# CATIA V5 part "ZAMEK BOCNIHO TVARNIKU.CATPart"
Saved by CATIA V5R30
Part number: ZAMEK BOCNIHO TVARNIKU
Bounding box of the stored display mesh (mm): x -1.29 to 19.5, y -8 to 17, z -7 to 7
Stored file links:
  C:\Users\ondra\Desktop\PŘÍLOHA P III\CATIA\ZAMEK BOCNIHO TVARNIKU.CATPart
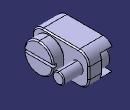
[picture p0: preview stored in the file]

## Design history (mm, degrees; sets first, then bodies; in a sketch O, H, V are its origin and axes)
Set1
  DatumSurface1 to DatumSurface36 "Z1899/8x"
  DatumSurface37 to DatumSurface64 "Z36/8x16"
  DatumSurface65 to DatumSurface93 "Z31/5x14"
  Plane1: type Offset, RefPlane zx-plane, Offset 17
  Join1: Elements (DatumSurface1; DatumSurface2; DatumSurface3; DatumSurface4; DatumSurface5; DatumSurface6; DatumSurface7; DatumSurface8; DatumSurface9; DatumSurface10; DatumSurface11; DatumSurface12; DatumSurface13; DatumSurface14; DatumSurface15; DatumSurface16; DatumSurface17; DatumSurface18; DatumSurface19; DatumSurface20; DatumSurface21; DatumSurface22; DatumSurface23; DatumSurface24; DatumSurface25; DatumSurface26; DatumSurface27; DatumSurface28; DatumSurface29; DatumSurface30; DatumSurface31; DatumSurface32; DatumSurface33; DatumSurface34; DatumSurface35; DatumSurface36)
  Join2: Elements (DatumSurface37; DatumSurface38; DatumSurface39; DatumSurface40; DatumSurface41; DatumSurface42; DatumSurface43; DatumSurface44; DatumSurface45; DatumSurface46; DatumSurface47; DatumSurface48; DatumSurface49; DatumSurface50; DatumSurface51; DatumSurface52; DatumSurface53; DatumSurface54; DatumSurface55; DatumSurface56; DatumSurface57; DatumSurface58; DatumSurface59; DatumSurface60; DatumSurface61; DatumSurface62; DatumSurface63; DatumSurface64)
  Join3: Elements (DatumSurface65; DatumSurface66; DatumSurface67; DatumSurface68; DatumSurface69; DatumSurface70; DatumSurface71; DatumSurface72; DatumSurface73; DatumSurface74; DatumSurface75; DatumSurface76; DatumSurface77; DatumSurface78; DatumSurface79; DatumSurface80; DatumSurface81; DatumSurface82; DatumSurface83; DatumSurface84; DatumSurface85; DatumSurface86; DatumSurface87; DatumSurface88; DatumSurface89; DatumSurface90; DatumSurface91; DatumSurface92; DatumSurface93)
Set2 "Geometry Failure"
  Set3 "FaceKO#Z31/5x14#2253"
    DatumSurface94 "Sur2253_1"
    Circle1 "Crv2253_1": stored without definition
    DatumCurve1 "PCrv2253_1"
    Circle2 "Crv2253_2": stored without definition
    DatumCurve2 "PCrv2253_2"
    Circle3 "Crv2253_3": stored without definition
    DatumCurve3 "PCrv2253_3"
    Circle4 "Crv2253_4": stored without definition
    DatumCurve4 "PCrv2253_4"
Body1 (main body)
  CloseSurface1: CloseElement Join1
  CloseSurface2: CloseElement Join2
  CloseSurface3: CloseElement Join3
